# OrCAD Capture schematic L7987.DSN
size D
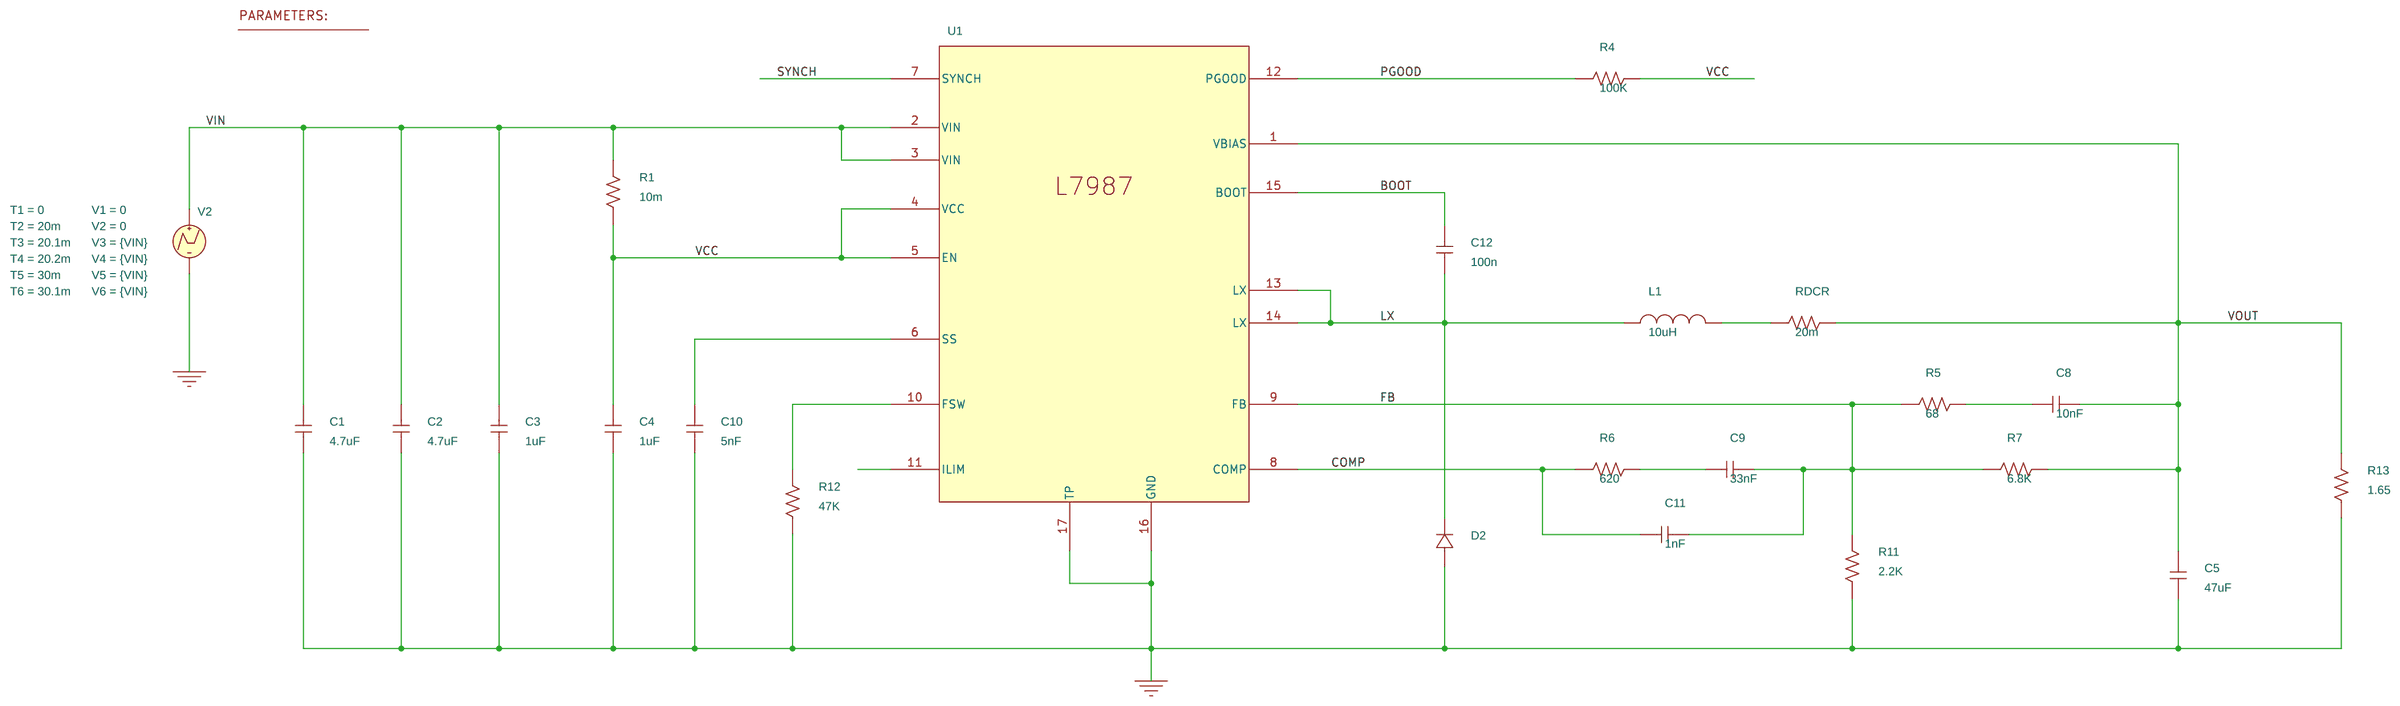
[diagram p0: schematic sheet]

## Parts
1  PARAM
C1  4.7uF  [RAD/CK05]
C2  4.7uF  [RAD/CK05]
C3  1uF  [RAD/CK05]
C4  1uF  [RAD/CK05]
C5  47uF  [RAD/CK05]
C8  10nF  [RAD/CK05]
C9  33nF  [RAD/CK05]
C10  5nF  [RAD/CK05]
C11  1nF  [RAD/CK05]
C12  100n  [RAD/CK05]
D2  power_Dbreak
L1  10uH  [DISC/.350x.175/LS.200x.100/.034]
R1  10m  [AX/RC05]
R4  100K  [AX/RC05]
R5  68  [AX/RC05]
R6  620  [AX/RC05]
R7  6.8K  [AX/RC05]
R11  2.2K  [AX/RC05]
R12  47K  [AX/RC05]
R13  1.65  [AX/RC05]
RDCR  20m  [AX/RC05]
U1  L7987
V2  VPWL

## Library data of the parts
1 = PARAM: VIN: 12
C1-C4 C10 C12 = C
C5 C8 C9 C11 = C: IC: 0
D2 = power_Dbreak
L1 = L
R1 R4-R7 R11-R13 RDCR = R
U1 = L7987
V2 = VPWL: T1: 0; T2: 20m; T3: 20.1m; T4: 20.2m; T5: 30m; T6: 30.1m; V1: 0; V2: 0; V3: {VIN}; V4: {VIN}; V5: {VIN}; V6: {VIN}

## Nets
VCC: C4.2 R1.1 R4.2 U1.4(VCC) U1.5(EN)
VIN: C1.2 C2.2 C3.2 R1.2 U1.2(VIN) U1.3(VIN) V2.1(+)
0: C1.1 C2.1 C3.1 C4.1 C5.1 C10.1 D2.0(1) R11.1 R12.1 R13.1 U1.16(GND) U1.17(TP) V2.2(-)
BOOT: C12.2 U1.15(BOOT)
COMP: C11.1 R6.1 U1.8(COMP)
FB: C9.2 C11.2 R5.1 R7.1 R11.2 U1.9(FB)
LX: C12.1 D2.1(2) L1.1 U1.13(LX) U1.14(LX)
PGOOD: R4.1 U1.12(PGOOD)
SYNCH: U1.7(SYNCH)
VOUT: C5.2 C8.2 R7.2 R13.2 RDCR.2 U1.1(VBIAS)
N3822602: C10.2 U1.6(SS)
N3823521: C9.1 R6.2
N3902903: C8.1 R5.2
N3925236: L1.2 RDCR.1
N3925746: R12.2 U1.10(FSW)

Not connected (* = marked no-connect by the designer): U1 11(ILIM)
